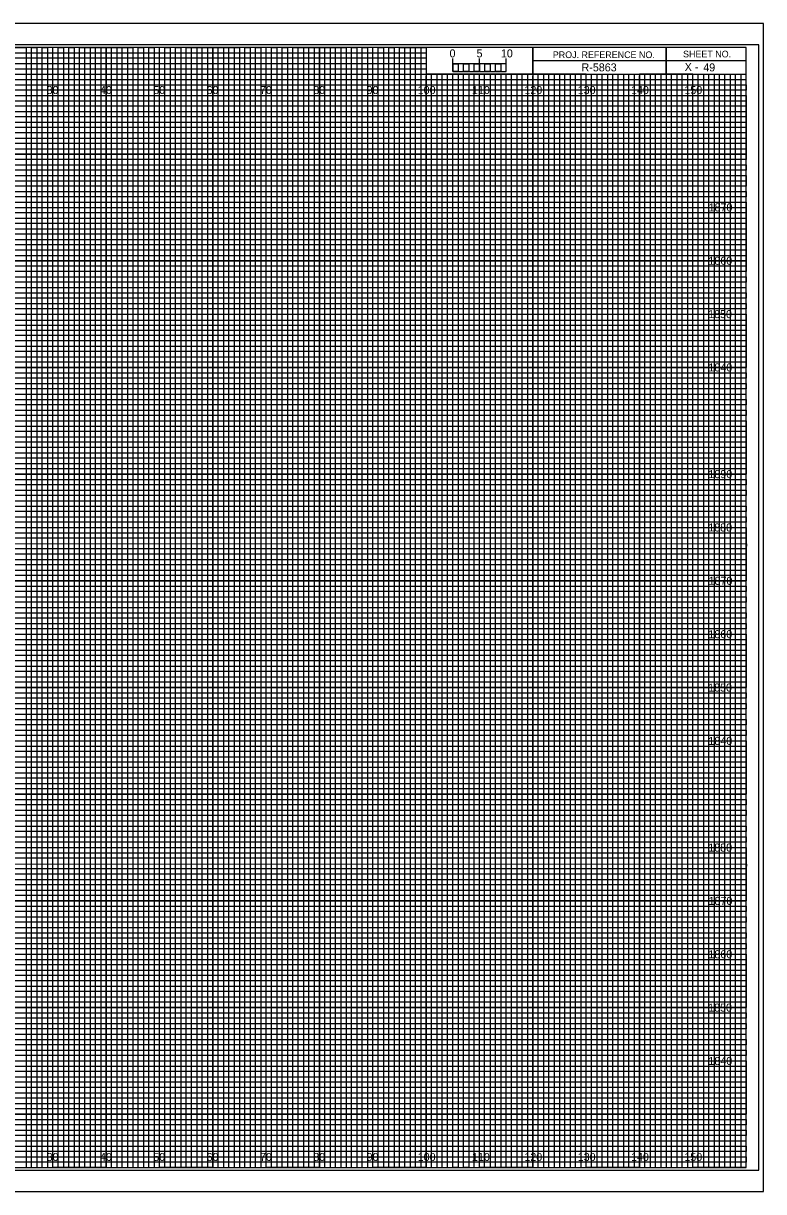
# Model space of a CAD drawing. Extents: x -13 to 323, y -4 to 214.
# Drawn here: x 184.5 to 323.3, y -4.5 to 214.5 of the extents above; entities that cross this region are included whole.
import ezdxf

# ---------------------------------------------------------------- set-up
doc = ezdxf.new("R2010")
doc.units = 0
for name, color, linetype in [('Prop XS Bar Scale Labels', 7, 'Continuous'), ('Prop XS Elevation Labels', 7, 'Continuous'), ('Prop XS Offset Labels', 7, 'Continuous'), ('Prop XS Project Number', 7, 'Continuous'), ('Prop XS Sheet Number', 7, 'Continuous'), ('Sheet Cross Section CELL', 7, 'Continuous'), ('Sheet Cross Section Grid Major CELL', 7, 'Continuous'), ('Sheet Cross Section Grid Middle CELL', 7, 'Continuous'), ('Sheet Cross Section Grid Minor 1 CELL', 7, 'Continuous'), ('Sheet Cross Section Grid Minor 2 CELL', 7, 'Continuous'), ('Sheet Cross Section Scale CELL', 7, 'Continuous'), ('Sheet Cutting Line CELL', 7, 'Continuous'), ('Sheet DOT Grid CELL', 7, 'Continuous'), ('Sheet Plot Border Inside CELL', 7, 'Continuous'), ('Sheet Plot Border Outside CELL', 7, 'Continuous')]:
    doc.layers.add(name, color=color, linetype=linetype)

msp = doc.modelspace()

# ---------------------------------------------------------------- linework, layer by layer
at = {"layer": 'Sheet Cross Section CELL'}
for p, q in [((305, 210), (305, 205)), ((305, 205), (305, 210)), ((280, 207.5), (280, 205)), ((320, 207.49), (280, 207.49)), ((280, 205), (320, 205))]:
    msp.add_line(p, q, dxfattribs=at)
for points in [[(320, 210), (0, 210), (0, 0), (320, 0)], [(280, 210), (260, 210), (260, 205.03), (280, 205.03)], [(320, 210), (280, 210), (280, 205), (320, 205)]]:
    msp.add_lwpolyline(points, close=True, dxfattribs=at)
at = {"layer": 'Sheet Cross Section Grid Major CELL'}
for p, q in [((190, 210), (180, 210)), ((190, 0), (190, 210)), ((210, 210), (200, 210)), ((200, 210), (200, 0)), ((210, 0), (210, 210)), ((230, 210), (220, 210)), ((220, 210), (220, 0)), ((230, 0), (230, 210)), ((250, 210), (240, 210)), ((240, 210), (240, 0)), ((250, 0), (250, 210)), ((260, 210), (260, 0)), ((270, 0), (270, 205)), ((290, 205), (280, 205)), ((280, 205), (280, 0)), ((290, 0), (290, 205)), ((310, 205), (300, 205)), ((300, 205), (300, 0)), ((310, 0), (310, 205)), ((200, 0), (190, 0)), ((220, 0), (210, 0)), ((240, 0), (230, 0)), ((260, 0), (250, 0)), ((280, 0), (270, 0)), ((300, 0), (290, 0)), ((320, 0), (310, 0)), ((320, 0), (320, 0))]:
    msp.add_line(p, q, dxfattribs=at)
for points in [[(0, 200), (320, 200), (320, 190), (0, 190)], [(0, 180), (320, 180), (320, 170), (0, 170)], [(0, 160), (320, 160), (320, 150), (0, 150)], [(0, 140), (320, 140), (320, 130), (0, 130)], [(0, 120), (320, 120), (320, 110), (0, 110)], [(0, 100), (320, 100), (320, 90), (0, 90)], [(0, 80), (320, 80), (320, 70), (0, 70)], [(0, 60), (320, 60), (320, 50), (0, 50)], [(0, 40), (320, 40), (320, 30), (0, 30)], [(0, 20), (320, 20), (320, 10), (0, 10)]]:
    msp.add_lwpolyline(points, dxfattribs=at)
at = {"layer": 'Sheet Cross Section Grid Middle CELL'}
for points in [[(175, 210), (185, 210), (185, 0), (195, 0), (195, 210), (205, 210), (205, 0), (215, 0), (215, 210), (225, 210), (225, 0), (235, 0), (235, 210), (245, 210), (245, 0), (255, 0), (255, 210), (259.93, 210), (260, 210), (260, 205), (264.99, 205), (264.99, 0), (275, 0), (275, 205), (285, 205), (285, 0), (295, 0), (295, 205), (305, 205), (305, 0), (315, 0), (315, 205)], [(0, 205), (275, 205)], [(0, 185), (320, 185), (320, 195), (0, 195)], [(0, 165), (320, 165), (320, 175), (0, 175)], [(0, 145), (320, 145), (320, 155), (0, 155)], [(0, 125), (320, 125), (320, 135), (0, 135)], [(0, 105), (320, 105), (320, 115), (0, 115)], [(0, 85), (320, 85), (320, 95), (0, 95)], [(0, 65), (320, 65), (320, 75), (0, 75)], [(0, 45), (320, 45), (320, 55), (0, 55)], [(0, 25), (320, 25), (320, 35), (0, 35)], [(0, 5), (320, 5), (320, 15), (0, 15)]]:
    msp.add_lwpolyline(points, dxfattribs=at)
at = {"layer": 'Sheet Cross Section Grid Minor 1 CELL'}
for p, q in [((0, 209), (260, 209)), ((260, 209), (260, 207.98)), ((260, 207.98), (0, 207.98)), ((0, 207), (260, 207)), ((260, 205.89), (0, 205.89)), ((260, 207), (260, 205.89)), ((0, 204), (320, 204))]:
    msp.add_line(p, q, dxfattribs=at)
for points in [[(0, 203), (270, 203), (320, 203), (320, 202), (0, 202)], [(0, 201), (320, 201), (320, 199), (0, 199)], [(0, 198), (320, 198), (320, 197), (0, 196.98)], [(0, 196), (320, 196), (320, 194), (0, 194)], [(0, 193), (320, 193), (320, 192), (0, 192)], [(0, 191), (320, 191), (320, 189), (0, 189)], [(0, 188), (320, 188), (320, 187), (0, 187)], [(0, 186), (320, 186), (320, 184), (0, 184)], [(0, 183), (320, 183), (320, 182), (0, 182)], [(0, 181), (320, 181), (320, 179), (0, 179)], [(0, 178), (320, 178), (320, 177), (0, 177)], [(0, 176), (320, 176), (320, 173.95), (320, 173), (320, 172), (0, 172)], [(0, 174), (320, 174), (320, 173), (0, 173)], [(0, 171), (320, 171), (320, 169), (0, 169.03)], [(0, 169.03), (320, 169), (320, 168), (0, 168)], [(0, 167), (320, 167), (320, 166), (0, 166)], [(0, 164), (320, 164), (320, 163), (0, 163)], [(0, 162), (320, 162), (320, 161), (0, 161)], [(-0.07, 158.89), (320, 158.89), (320, 157.88), (-0.07, 157.88)], [(0, 157), (320, 157), (320, 156), (0, 156)], [(0, 154), (320, 154), (320, 153), (0, 153)], [(0, 152), (320, 152), (320, 151), (0, 151)], [(0, 149), (320, 149), (320, 148), (0, 148)], [(0, 147), (320, 147), (320, 146), (0, 146)], [(0, 144), (320, 144), (320, 143), (0, 143)], [(0, 142), (320, 142), (320, 141), (0, 141)], [(0, 139), (320, 139), (319.99, 137.98), (0, 138)], [(0, 137), (320, 137), (320, 136), (0, 136)], [(0, 134), (320, 134), (320, 133), (0, 133)], [(0, 132), (320, 132), (320, 131), (0, 131)], [(0, 129), (320, 129), (320, 128), (0, 128)], [(0, 127), (320, 127), (320, 126), (0, 126)], [(0, 124), (320, 124), (320, 123), (0, 123)], [(0, 122), (320, 122), (320, 121), (0, 121)], [(0, 119), (320, 119), (320, 118), (0, 118)], [(0, 116.99), (320.07, 116.91), (320, 116), (0, 116)], [(0, 114), (320, 114), (320, 113), (0, 113)], [(0, 112), (320, 112), (320, 111), (0, 111)], [(0, 109), (320, 109), (320, 108), (0, 108)], [(0, 107), (320, 107), (320, 106), (0, 106)], [(0, 104), (320, 104), (320, 103), (0, 103)], [(0, 102), (320, 102), (320, 101), (0, 101)], [(0, 99), (320, 99), (320, 98), (0, 98)], [(0, 97), (320, 97), (320, 96), (0, 96)], [(0, 94), (320, 94), (320, 93), (0, 93)], [(0, 92), (320, 92), (320, 91), (0, 91)], [(0, 89), (320, 89), (320, 88), (0, 88)], [(0, 87), (320, 87), (320, 86), (0, 86)], [(0, 84), (320, 84), (320, 83), (0, 83)], [(0, 82), (320, 82), (320, 81), (0, 81)], [(0, 79), (320, 79), (319.99, 77.98), (0, 78)], [(0, 77), (320, 77), (320, 76), (0, 76)], [(0, 74), (320, 74), (320, 73), (0, 73)], [(0, 72), (320, 72), (320, 71), (0, 71)], [(0, 69), (320, 69), (320, 68), (0, 68)], [(0, 67), (320, 67), (320, 66), (0, 66)], [(0, 64), (320, 64), (320, 63), (0, 63)], [(0, 62), (320, 62), (320, 61), (0, 61)], [(0, 59), (320, 59), (320, 58), (0, 58)], [(0, 56.99), (320.07, 56.91), (320, 56), (0, 56)], [(0, 54), (320, 54), (320, 53), (0, 53)], [(0, 52), (320, 52), (320, 51), (0, 51)], [(0, 49), (320, 49), (320, 48), (0, 48)], [(0, 47), (320, 47), (320, 46), (0, 46)], [(0, 44), (320, 44), (320, 43), (0, 43)], [(0, 42), (320, 42), (320, 41), (0, 41)], [(0, 39), (320, 39), (320, 38), (0, 38)], [(0, 37), (320, 37), (320, 36), (0, 36)], [(0, 34), (320, 34), (320, 33), (0, 33)], [(0, 32), (320, 32), (320, 31), (0, 31)], [(0, 29), (320, 29), (320, 28), (0, 28)], [(0, 27), (320, 27), (320, 26), (0, 26)], [(0, 24), (320, 24), (320, 23), (0, 23)], [(0, 22), (320, 22), (320, 21), (0, 21)], [(0, 19), (320, 19), (320, 18), (0, 18)], [(0, 17), (320, 17), (320, 16), (0, 16)], [(0, 14), (320, 14), (320, 13), (0, 13)], [(0, 12), (320, 12), (320, 11), (0, 11)], [(0, 9), (320, 9), (320, 8), (0, 8)], [(0, 7), (320, 7), (320, 6), (0, 6)], [(0, 4), (320, 4), (320, 3), (0, 3)], [(0, 2), (320, 2), (320, 1), (0, 1)]]:
    msp.add_lwpolyline(points, dxfattribs=at)
at = {"layer": 'Sheet Cross Section Grid Minor 2 CELL'}
for p, q in [((267, 205), (266.01, 205)), ((266.01, 205), (266.01, 0)), ((267, 0), (267, 205)), ((269, 205), (268, 205)), ((268, 205), (268, 0)), ((269, 0), (269, 205)), ((266.01, 0), (265, 0)), ((268, 0), (267, 0))]:
    msp.add_line(p, q, dxfattribs=at)
for points in [[(185, 0), (186, 0), (186, 210), (187, 210), (187, 0)], [(187, 0), (188, 0), (188, 210), (189, 210), (189, 0)], [(190, 0), (191, 0), (191, 210), (192, 210), (192, 0)], [(192, 0), (193, 0), (193, 210), (194, 210), (194, 0)], [(195, 0), (196, 0), (196, 210), (197, 210), (197, 0)], [(197, 0), (198, 0), (198, 210), (199, 210), (199, 0)], [(200, 0), (201, 0), (201, 210), (202, 210), (202, 0)], [(202, 0), (203, 0), (203, 210), (204, 210), (204, 0)], [(205, 0), (206, 0), (206, 210), (207, 210), (207, 0)], [(207, 0), (208, 0), (208, 210), (209, 210), (209, 0)], [(210, 0), (211, 0), (211, 210), (212, 210), (212, 0)], [(212, 0), (213, 0), (213, 210), (214, 210), (214, 0)], [(215, 0), (216, 0), (216, 210), (217, 210), (217, 0)], [(217, 0), (218, 0), (218, 210), (219, 210), (219, 0)], [(220, 0), (221, 0), (221, 210), (222, 210), (222, 0)], [(222, 0), (223, 0), (223, 210), (224, 210), (224, 0)], [(225, 0), (226, 0), (226, 210), (227, 210), (227, 0)], [(227, 0), (228, 0), (228, 210), (229, 210), (229, 0)], [(230, 0), (231, 0), (231, 210), (232, 210), (232, 0)], [(232, 0), (233, 0), (233, 210), (234, 210), (234, 0)], [(235, 0), (236, 0), (236, 210), (237, 210), (237, 0)], [(237, 0), (238, 0), (238, 210), (239, 210), (239, 0)], [(240, 0), (241, 0), (241, 210), (242, 210), (242, 0)], [(242, 0), (243, 0), (243, 210), (244, 210), (244, 0)], [(245, 0), (246, 0), (246, 210), (247, 210), (247, 0)], [(247, 0), (248, 0), (248, 210), (249, 210), (249, 0)], [(250, 0), (251, 0), (251, 210), (252, 210), (252, 0)], [(252, 0), (253, 0), (253, 210), (254, 210), (254, 0)], [(255, 0), (256, 0), (256, 210), (257, 210), (257, 0)], [(257, 0), (258, 0), (258, 210), (259, 210), (259, 0)], [(260, 0), (261, 0), (261, 205), (262.02, 205), (262.02, 0)], [(262, 0), (263, 0), (263, 205), (263.99, 205), (263.99, 0)], [(270, 0), (270.98, 0), (270.98, 205), (272, 205), (272, 0)], [(272, 0), (273, 0), (273, 205), (274.05, 205), (274.05, 0)], [(275, 0), (276, 0), (276, 205), (277, 205), (277, 0)], [(277, 0), (278, 0), (278, 205), (279, 205), (279, 0)], [(280, 0), (281, 0), (281, 205), (282, 205), (282, 0)], [(282, 0), (283, 0), (283, 205), (284, 205), (284, 0)], [(285, 0), (286, 0), (286, 205), (287, 205), (287, 0)], [(287, 0), (288, 0), (288, 205), (289, 205), (289, 0)], [(290, 0), (291, 0), (291, 205), (292, 205), (292, 0)], [(292, 0), (293, 0), (293, 205), (294, 205), (294, 0)], [(295, 0), (296, 0), (296, 205), (297, 205), (297, 0)], [(297, 0), (298, 0), (298, 205), (299, 205), (299, 0)], [(300, 0), (301, 0), (301, 205), (302, 205), (302, 0)], [(302, 0), (303, 0), (303, 205), (304, 205), (304, 0)], [(305, 0), (306, 0), (306, 205), (307, 205), (307, 0)], [(307, 0), (308, 0), (308, 205), (309, 205), (309, 0)], [(310, 0), (311, 0), (311, 205), (312, 205), (312, 0)], [(312, 0), (313, 0), (313, 205), (314, 205), (314, 0)], [(315, 0), (316, 0), (316, 205), (317, 205), (317, 0)], [(317, 0), (318, 0), (318, 205), (319, 205), (319, 0)]]:
    msp.add_lwpolyline(points, dxfattribs=at)
at = {"layer": 'Sheet Cross Section Scale CELL'}
for p, q in [((265, 205.49), (265, 207.9)), ((265, 206.9), (265, 207.9)), ((270, 205.49), (270, 207.9)), ((275, 205.49), (275, 207.9)), ((275, 206.9), (275, 207.9))]:
    msp.add_line(p, q, dxfattribs=at)
for points in [[(275, 206.9), (265, 206.9), (265, 205.49), (275, 205.49)], [(265, 206.9), (266, 206.9), (266, 205.49), (265, 205.49)], [(267, 206.9), (268, 206.9), (268, 205.49), (267, 205.49)], [(269, 206.9), (270, 206.9), (270, 205.49), (269, 205.49)], [(271, 206.9), (272, 206.9), (272, 205.49), (271, 205.49)], [(273, 206.9), (274, 206.9), (274, 205.49), (273, 205.49)]]:
    msp.add_lwpolyline(points, close=True, dxfattribs=at)
at = {"layer": 'Sheet Cutting Line CELL'}
for p, q in [((323.3, 214.5), (-13.4, 214.5)), ((-13.4, -4.5), (323.3, -4.5))]:
    msp.add_line(p, q, dxfattribs=at)
at = {"layer": 'Sheet DOT Grid CELL'}
for p, q in [((190, 0), (190, 210)), ((200, 0), (200, 210)), ((210, 0), (210, 210)), ((220, 0), (220, 210)), ((230, 0), (230, 210)), ((240, 0), (240, 210)), ((250, 0), (250, 210)), ((260, 0), (260, 204.69)), ((270, 0), (270, 204.69)), ((280, 0), (280, 204.69)), ((290, 0), (290, 204.69)), ((300, 0), (300, 204.69)), ((310, 0), (310, 204.69)), ((0, 200), (320, 200)), ((0, 190), (320, 190)), ((0, 180), (320, 180)), ((0, 170), (320, 170)), ((0, 160), (320, 160)), ((0, 150), (320, 150)), ((0, 140), (320, 140)), ((0, 130), (320, 130)), ((0, 120), (320, 120)), ((0, 110), (320, 110)), ((0, 100), (320, 100)), ((0, 90), (320, 90)), ((0, 80), (320, 80)), ((0, 70), (320, 70)), ((0, 60), (320, 60)), ((0, 50), (320, 50)), ((0, 40), (320, 40)), ((0, 30), (320, 30)), ((0, 20), (320, 20)), ((0, 10), (320, 10))]:
    msp.add_line(p, q, dxfattribs=at)
at = {"layer": 'Sheet Plot Border Inside CELL'}
msp.add_lwpolyline([(-10.8, -0.5), (322.4, -0.5), (322.4, 210.5), (-10.8, 210.5)], close=True, dxfattribs=at)
at = {"layer": 'Sheet Plot Border Outside CELL'}
msp.add_lwpolyline([(-13.4, -4.5), (323.3, -4.5), (323.3, 214.5), (-13.4, 214.5)], close=True, dxfattribs=at)

# ---------------------------------------------------------------- texts
at = {"layer": 'Prop XS Bar Scale Labels'}
for s, p in [('5', (269.47, 208.12)), ('10', (274.04, 208.12))]:
    msp.add_text(s, height=1.5, dxfattribs=at).set_placement(p)
at = {"layer": 'Prop XS Elevation Labels'}
for s, p in [('1870', (312.98, 179.25)), ('1860', (312.95, 169.25)), ('1850', (312.9, 159.25)), ('1840', (312.95, 149.25)), ('1890', (312.95, 129.25)), ('1880', (312.92, 119.25)), ('1870', (312.98, 109.25)), ('1860', (312.95, 99.25)), ('1850', (312.9, 89.25)), ('1840', (312.95, 79.25)), ('1880', (312.92, 59.25)), ('1870', (312.98, 49.25)), ('1860', (312.95, 39.25)), ('1850', (312.9, 29.25)), ('1840', (312.95, 19.25))]:
    msp.add_text(s, height=1.5, dxfattribs=at).set_placement(p)
at = {"layer": 'Prop XS Offset Labels'}
for s, p in [('30', (188.86, 201.25)), ('40', (198.86, 201.25)), ('50', (208.86, 201.25)), ('60', (218.86, 201.25)), ('70', (228.86, 201.25)), ('80', (238.86, 201.25)), ('90', (248.86, 201.25)), ('100', (258.44, 201.25)), ('110', (268.62, 201.25)), ('120', (278.44, 201.25)), ('130', (288.44, 201.25)), ('140', (298.44, 201.25)), ('150', (308.44, 201.25)), ('30', (188.86, 1.25)), ('40', (198.86, 1.25)), ('50', (208.86, 1.25)), ('60', (218.86, 1.25)), ('70', (228.86, 1.25)), ('80', (238.86, 1.25)), ('90', (248.86, 1.25)), ('100', (258.44, 1.25)), ('110', (268.62, 1.25)), ('120', (278.44, 1.25)), ('130', (288.44, 1.25)), ('140', (298.44, 1.25)), ('150', (308.44, 1.25))]:
    msp.add_text(s, height=1.5, dxfattribs=at).set_placement(p)
at = {"layer": 'Prop XS Project Number'}
msp.add_text('R-5863', height=1.5, dxfattribs=at).set_placement((289.16, 205.5))
at = {"layer": 'Prop XS Sheet Number'}
msp.add_text('49', height=1.5, dxfattribs=at).set_placement((311.98, 205.5))
at = {"layer": 'Sheet Cross Section CELL'}
for s, height, p in [('PROJ. REFERENCE NO.', 1.25, (283.77, 207.99)), ('SHEET NO.', 1.25, (308.19, 208.12)), ('X -    ', 1.5, (308.5, 205.58))]:
    msp.add_text(s, height=height, dxfattribs=at).set_placement(p)
at = {"layer": 'Sheet Cross Section Scale CELL'}
msp.add_text('0', height=1.5, dxfattribs=at).set_placement((264.41, 208.12))

doc.saveas('drawing.dxf')
